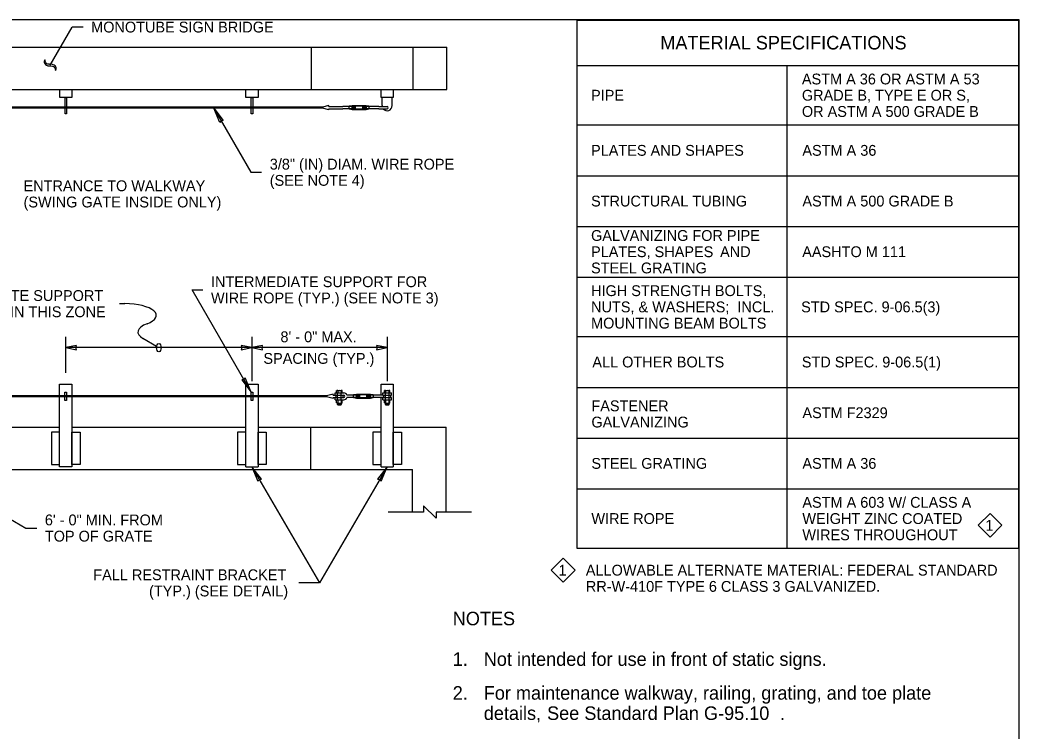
# Model space of a CAD drawing. Extents: x 99862 to 103151, y 100000 to 108076.
# Drawn here: x 101674 to 103151, y 101024 to 102076 of the extents above; entities that cross this region are included whole.
import ezdxf

# ---------------------------------------------------------------- set-up
doc = ezdxf.new("R2010")
doc.units = 0
for name, color, linetype in [('Level 1', 7, 'Continuous'), ('Level 11', 7, 'Continuous'), ('Level 14', 7, 'Continuous'), ('Level 15', 7, 'Continuous'), ('Level 18', 7, 'Continuous'), ('Level 2', 7, 'Continuous'), ('Level 20', 7, 'Continuous'), ('Level 23', 7, 'Continuous'), ('Level 3', 7, 'Continuous'), ('Level 4', 7, 'Continuous'), ('Level 60', 7, 'Continuous')]:
    doc.layers.add(name, color=color, linetype=linetype)

msp = doc.modelspace()

# ---------------------------------------------------------------- linework, layer by layer
at = {"layer": 'Level 1'}
msp.add_lwpolyline([(99862, 99999.5), (103151, 99999.5), (103151, 102075.5), (99862, 102075.5)], close=True, dxfattribs=at)
at = {"layer": 'Level 11'}
for p, q in [((102209.5, 101948.8), (102209.5, 101960.8)), ((102224.4, 101948.8), (102224.4, 101960.8)), ((102113.5, 101946.7), (101486.1, 101946.7)), ((102113.5, 101945), (101486.1, 101945)), ((102121.2, 101946.7), (102113.5, 101946.7)), ((102121.2, 101945), (102113.5, 101945)), ((102130.5, 101949.2), (102121.2, 101946.7)), ((102121.2, 101946.7), (102121.2, 101945)), ((102130.5, 101942.5), (102121.2, 101945)), ((102130.5, 101947.5), (102130.5, 101949.2)), ((102130.5, 101947.5), (102151.1, 101947.5)), ((102130.5, 101944.2), (102151.1, 101944.2)), ((102130.5, 101942.5), (102130.5, 101944.2)), ((102160.8, 101947.5), (102151.1, 101947.5)), ((102160.8, 101944.2), (102151.1, 101944.2)), ((102165.1, 101947.5), (102160.8, 101947.5)), ((102165.1, 101944.2), (102160.8, 101944.2)), ((102165.1, 101948.3), (102185.7, 101948.3)), ((102165.1, 101943.4), (102165.1, 101948.3)), ((102165.1, 101947.5), (102170, 101947.5)), ((102165.1, 101944.2), (102170, 101944.2)), ((102185.7, 101943.4), (102165.1, 101943.4)), ((102165.9, 101945), (102165.9, 101946.7)), ((102166.7, 101944.2), (102166.7, 101947.5)), ((102167.6, 101945), (102167.6, 101946.7)), ((102168.4, 101944.2), (102168.4, 101947.5)), ((102169.2, 101945), (102169.2, 101946.7)), ((102170, 101944.2), (102170, 101947.5)), ((102185.7, 101947.5), (102180.7, 101947.5)), ((102180.7, 101944.2), (102180.7, 101947.5)), ((102185.7, 101944.2), (102180.7, 101944.2)), ((102181.5, 101945), (102181.5, 101946.7)), ((102182.3, 101944.2), (102182.3, 101947.5)), ((102183.2, 101945), (102183.2, 101946.7)), ((102184, 101944.2), (102184, 101947.5)), ((102184.8, 101945), (102184.8, 101946.7)), ((102185.7, 101948.3), (102185.7, 101943.4)), ((102189.9, 101947.5), (102185.7, 101947.5)), ((102189.9, 101944.2), (102185.7, 101944.2)), ((102204.4, 101947.5), (102189.9, 101947.5)), ((102204.4, 101944.2), (102189.9, 101944.2)), ((102204.4, 101947.5), (102216.9, 101947.5)), ((102204.4, 101944.2), (102216.9, 101944.2))]:
    msp.add_line(p, q, dxfattribs=at)
for points in [[(101740.8, 101960.8), (101743, 101960.8), (101743, 101936.8), (101740.8, 101936.8)], [(102015.8, 101960.8), (102018.1, 101960.8), (102018.1, 101936.8), (102015.8, 101936.8)], [(102160.8, 101948.3), (102165, 101949.2), (102185.7, 101949.2), (102189.9, 101948.3), (102189.9, 101943.4), (102185.7, 101942.5), (102165, 101942.5), (102160.8, 101943.4)], [(101740.5, 101525), (101742.8, 101525), (101742.8, 101513), (101740.5, 101513)], [(102015.8, 101525), (102018.1, 101525), (102018.1, 101513), (102015.8, 101513)]]:
    msp.add_lwpolyline(points, close=True, dxfattribs=at)
for centre, radius, start, end in [((102216.9, 101948.8), 7.45, 180, 190.3619), ((102216.9, 101948.8), 7.45, 218.7191, 0), ((102216.9, 101945.8), 1.66, 270, 90)]:
    msp.add_arc(centre, radius, start, end, dxfattribs=at)
at = {"layer": 'Level 14'}
msp.add_line((101821.1, 101656), (101829.1, 101656), dxfattribs=at)
for centre, start_param, end_param in [((101829.1, 101638.6), 2.356226, 4.712389), ((101894.7, 101614), 5.497747, 6.859209)]:
    msp.add_ellipse(centre, major_axis=(-46.4, 0), ratio=0.375, start_param=start_param, end_param=end_param, dxfattribs=at)
at = {"layer": 'Level 15'}
for p, q in [((101718.7, 102008.7), (101751.2, 102065)), ((101767.2, 102065), (101751.2, 102065)), ((101960.6, 101945), (102015.3, 101850.3)), ((102015.3, 101850.3), (102031.3, 101850.3)), ((102015.8, 101525), (101928.4, 101676.4)), ((101928.4, 101676.4), (101944.4, 101676.4)), ((101741.6, 101553.5), (101741.6, 101607)), ((101876, 101592.9), (101855.8, 101604.5)), ((102017, 101607), (102017, 101541.5)), ((102216.9, 101607), (102216.9, 101541.5)), ((102017, 101591), (101741.6, 101591)), ((102216.9, 101591), (102017, 101591)), ((102017, 101414.8), (102116.9, 101243)), ((102216.9, 101414.8), (102116.9, 101243)), ((101605.6, 101368.7), (101682.8, 101324.2)), ((101682.8, 101324.2), (101698.8, 101324.2)), ((102116.9, 101243), (102086.3, 101243))]:
    msp.add_line(p, q, dxfattribs=at)
for points in [[(101960.6, 101945), (101974.6, 101926.7), (101971.5, 101926.2), (101969.4, 101923.7)], [(101741.6, 101591), (101757.4, 101587.9), (101756.6, 101591), (101757.4, 101594.1)], [(102017, 101591), (102001.2, 101594.1), (102002, 101591), (102001.2, 101587.9)], [(102017, 101591), (102032.7, 101587.9), (102032, 101591), (102032.7, 101594.1)], [(102017, 101591), (102032.7, 101587.9), (102032, 101591), (102032.7, 101594.1)], [(102216.9, 101591), (102201.2, 101594.1), (102201.9, 101591), (102201.2, 101587.9)], [(102015.8, 101525), (102007, 101546.3), (102005, 101543.8), (102001.8, 101543.3)], [(102017, 101414.8), (102025.9, 101393.5), (102027.9, 101395.9), (102031, 101396.5)], [(102216.9, 101414.8), (102202.8, 101396.5), (102205.9, 101395.9), (102208, 101393.5)]]:
    msp.add_lwpolyline(points, close=True, dxfattribs=at)
msp.add_lwpolyline([(102341.3, 101347.9), (102289.1, 101347.9), (102289.1, 101338.6), (102270.5, 101357.2), (102270.5, 101347.9), (102218.2, 101347.9)], dxfattribs=at)
msp.add_ellipse((101879.3, 101591), major_axis=(0, 6), ratio=0.57735, dxfattribs=at)
at = {"layer": 'Level 18'}
for p, q in [((102008, 101414.8), (102026, 101414.8)), ((102207.9, 101414.8), (102225.9, 101414.8))]:
    msp.add_line(p, q, dxfattribs=at)
for points in [[(101732.6, 101519.8), (101732.6, 101537), (101750.6, 101537), (101750.6, 101519.8)], [(102008, 101519.8), (102008, 101537), (102026, 101537), (102026, 101519.8)], [(102207.9, 101520.6), (102207.9, 101537), (102225.9, 101537), (102225.9, 101537)], [(102225.9, 101537), (102225.9, 101414.8)], [(101750.6, 101518.2), (101750.6, 101414.8), (101732.6, 101414.8), (101732.6, 101518.2)], [(102008, 101414.8), (102008, 101518.2)], [(102026, 101518.2), (102026, 101414.8)], [(102207.9, 101414.8), (102207.9, 101517.3)]]:
    msp.add_lwpolyline(points, dxfattribs=at)
for points in [[(101732.6, 101466.2), (101720.4, 101466.2), (101720.4, 101418.3), (101732.6, 101418.3)], [(101750.6, 101466.2), (101762.8, 101466.2), (101762.8, 101418.3), (101750.6, 101418.3)], [(102008, 101466.2), (101995.8, 101466.2), (101995.8, 101418.3), (102008, 101418.3)], [(102026, 101466.2), (102038.2, 101466.2), (102038.2, 101418.3), (102026, 101418.3)], [(102207.9, 101466.2), (102195.7, 101466.2), (102195.7, 101418.3), (102207.9, 101418.3)], [(102225.9, 101466.2), (102238.1, 101466.2), (102238.1, 101418.3), (102225.9, 101418.3)]]:
    msp.add_lwpolyline(points, close=True, dxfattribs=at)
at = {"layer": 'Level 2'}
for p, q in [((101510.2, 102035.3), (102305.1, 102035.3)), ((102105.1, 101972.8), (102105.1, 102035.3)), ((102255.1, 101972.8), (102255.1, 102035.3)), ((102305.1, 101972.8), (102305.1, 102035.3)), ((102305.1, 101972.8), (102305.1, 102035.3)), ((101510.2, 101972.8), (102305.1, 101972.8)), ((101509.1, 101473.5), (101732.6, 101473.5)), ((101750.6, 101473.5), (102008, 101473.5)), ((102026, 101473.5), (102207.9, 101473.5)), ((102104.1, 101411), (102104.1, 101473.5)), ((102225.9, 101473.5), (102304.1, 101473.5)), ((102304.1, 101347.9), (102304.1, 101473.5)), ((101509.1, 101411), (102254.1, 101411)), ((102254.1, 101347.9), (102254.1, 101411))]:
    msp.add_line(p, q, dxfattribs=at)
at = {"layer": 'Level 20'}
for p, q in [((101710.7, 102016.6), (101709.7, 102014.8)), ((101711.7, 102013.1), (101710.7, 102016.6)), ((101709.7, 102014.8), (101710, 102012.7)), ((101710, 102012.7), (101710.7, 102011)), ((101710.7, 102011), (101711.6, 102009.7)), ((101711.6, 102009.7), (101713, 102008.7)), ((101712.6, 102011.7), (101711.7, 102013.1)), ((101713.7, 102010.7), (101712.6, 102011.7)), ((101713, 102008.7), (101715.3, 102007.8)), ((101715.1, 102010.2), (101713.7, 102010.7)), ((101717.5, 102010), (101715.1, 102010.2)), ((101715.3, 102007.8), (101719.3, 102007.5)), ((101721.9, 102009.6), (101717.5, 102010)), ((101719.3, 102007.5), (101721.9, 102007.3)), ((101724.4, 102008.7), (101721.9, 102009.6)), ((101721.9, 102007.3), (101723.7, 102006.7)), ((101723.7, 102006.7), (101724.7, 102005.9)), ((101725.8, 102007.6), (101724.4, 102008.7)), ((101724.7, 102005.9), (101725.6, 102004.8)), ((101725.6, 102004.8), (101726.2, 102003.2)), ((101726.9, 102006.3), (101725.8, 102007.6)), ((101726.2, 102003.2), (101726.7, 102000.8)), ((101726.7, 102000.8), (101727.7, 102002.6)), ((101727.5, 102004.6), (101726.9, 102006.3)), ((101727.7, 102002.6), (101727.5, 102004.6))]:
    msp.add_line(p, q, dxfattribs=at)
for points in [[(103108.1, 101345.8), (103125.7, 101328.3), (103108.1, 101310.7), (103090.6, 101328.3)], [(102477, 101279.5), (102494.6, 101261.9), (102477, 101244.4), (102459.5, 101261.9)]]:
    msp.add_lwpolyline(points, close=True, dxfattribs=at)
at = {"layer": 'Level 23'}
for points in [[(101732.9, 101972.8), (101750.9, 101972.8), (101750.9, 101960.8), (101732.9, 101960.8)], [(102008, 101972.8), (102026, 101972.8), (102026, 101960.8), (102008, 101960.8)], [(102207.9, 101972.8), (102225.9, 101972.8), (102225.9, 101960.8), (102207.9, 101960.8)]]:
    msp.add_lwpolyline(points, close=True, dxfattribs=at)
at = {"layer": 'Level 3'}
for p, q in [((102497.7, 102008.3), (103150, 102008.3)), ((102807.8, 102008.3), (102807.8, 101294.1)), ((102497.7, 101920.2), (103150, 101920.2)), ((102497.7, 101845.2), (103150, 101845.2)), ((102497.7, 101770.3), (103150, 101770.3)), ((102497.7, 101695.3), (103150, 101695.3)), ((102497.7, 101607.2), (103150, 101607.2)), ((102497.7, 101532.2), (103150, 101532.2)), ((102497.7, 101457.3), (103150, 101457.3)), ((102497.7, 101382.3), (103150, 101382.3))]:
    msp.add_line(p, q, dxfattribs=at)
msp.add_lwpolyline([(102497.7, 102075), (103150, 102075), (103150, 101294.1), (102497.7, 101294.1)], close=True, dxfattribs=at)
at = {"layer": 'Level 4'}
for p, q in [((102119.8, 101519.8), (101480.4, 101519.8)), ((102119.8, 101518.2), (101480.4, 101518.2)), ((102127.4, 101519.8), (102119.8, 101519.8)), ((102127.4, 101518.2), (102119.8, 101518.2)), ((102136.8, 101522.3), (102127.4, 101519.8)), ((102127.4, 101519.8), (102127.4, 101518.2)), ((102136.8, 101515.7), (102127.4, 101518.2)), ((102136.8, 101520.6), (102136.8, 101522.3)), ((102136.8, 101520.6), (102152.6, 101520.6)), ((102136.8, 101517.3), (102152.6, 101517.3)), ((102136.8, 101515.7), (102136.8, 101517.3)), ((102140.1, 101524), (102152.6, 101524)), ((102140.1, 101520.6), (102140.1, 101524)), ((102140.1, 101514), (102140.1, 101517.3)), ((102140.1, 101514), (102152.6, 101514)), ((102142.2, 101524), (102142.2, 101527.4)), ((102142.2, 101514), (102150.5, 101514)), ((102142.2, 101509.2), (102142.2, 101514)), ((102143.1, 101527.7), (102149.6, 101527.7)), ((102143.6, 101514), (102143.6, 101524)), ((102144, 101527.4), (102144, 101524)), ((102144, 101514), (102144, 101509.2)), ((102148.7, 101527.4), (102148.7, 101524)), ((102148.7, 101514), (102148.7, 101509.2)), ((102149.1, 101514), (102149.1, 101524)), ((102150.5, 101524), (102150.5, 101527.4)), ((102150.5, 101509.2), (102150.5, 101514)), ((102167.1, 101520.6), (102157.4, 101520.6)), ((102167.1, 101517.3), (102157.4, 101517.3)), ((102171.3, 101520.6), (102167.1, 101520.6)), ((102171.3, 101517.3), (102167.1, 101517.3)), ((102171.3, 101521.5), (102191.9, 101521.5)), ((102171.3, 101516.5), (102171.3, 101521.5)), ((102171.3, 101520.6), (102176.3, 101520.6)), ((102171.3, 101517.3), (102176.3, 101517.3)), ((102191.9, 101516.5), (102171.3, 101516.5)), ((102172.2, 101518.2), (102172.2, 101519.8)), ((102173, 101517.3), (102173, 101520.6)), ((102173.8, 101518.2), (102173.8, 101519.8)), ((102174.7, 101517.3), (102174.7, 101520.6)), ((102175.5, 101518.2), (102175.5, 101519.8)), ((102176.3, 101517.3), (102176.3, 101520.6)), ((102191.9, 101520.6), (102186.9, 101520.6)), ((102186.9, 101517.3), (102186.9, 101520.6)), ((102191.9, 101517.3), (102186.9, 101517.3)), ((102187.8, 101518.2), (102187.8, 101519.8)), ((102188.6, 101517.3), (102188.6, 101520.6)), ((102189.4, 101518.2), (102189.4, 101519.8)), ((102190.3, 101517.3), (102190.3, 101520.6)), ((102191.1, 101518.2), (102191.1, 101519.8)), ((102191.9, 101521.5), (102191.9, 101516.5)), ((102196.2, 101520.6), (102191.9, 101520.6)), ((102196.2, 101517.3), (102191.9, 101517.3)), ((102210.6, 101520.6), (102196.2, 101520.6)), ((102210.6, 101517.3), (102196.2, 101517.3)), ((102210.6, 101524), (102223.2, 101524)), ((102210.6, 101520.6), (102210.6, 101524)), ((102210.6, 101520.6), (102223.2, 101520.6)), ((102210.6, 101517.3), (102223.2, 101517.3)), ((102210.6, 101514), (102210.6, 101517.3)), ((102210.6, 101514), (102223.2, 101514)), ((102212.8, 101524), (102212.8, 101527.4)), ((102212.8, 101514), (102221, 101514)), ((102212.8, 101509.2), (102212.8, 101514)), ((102213.6, 101527.7), (102220.1, 101527.7)), ((102214.2, 101514), (102214.2, 101524)), ((102214.5, 101527.4), (102214.5, 101524)), ((102214.5, 101514), (102214.5, 101509.2)), ((102219.3, 101527.4), (102219.3, 101524)), ((102219.3, 101514), (102219.3, 101509.2)), ((102219.6, 101514), (102219.6, 101524)), ((102221, 101524), (102221, 101527.4)), ((102221, 101509.2), (102221, 101514)), ((102223.2, 101520.6), (102223.2, 101524)), ((102223.2, 101514), (102223.2, 101517.3)), ((102143.1, 101508.9), (102149.6, 101508.9)), ((102143.6, 101506.9), (102143.6, 101508.9)), ((102143.6, 101507.9), (102149.1, 101507.9)), ((102143.6, 101506.9), (102149.1, 101506.9)), ((102143.6, 101506.9), (102143.9, 101506.4)), ((102143.9, 101506.4), (102148.8, 101506.4)), ((102144.4, 101508.4), (102148.3, 101508.4)), ((102144.4, 101507.4), (102148.3, 101507.4)), ((102149.1, 101506.9), (102148.8, 101506.4)), ((102149.1, 101506.9), (102149.1, 101508.9)), ((102213.6, 101508.9), (102220.1, 101508.9)), ((102214.2, 101506.9), (102214.2, 101508.9)), ((102214.2, 101507.9), (102219.6, 101507.9)), ((102214.2, 101506.9), (102219.6, 101506.9)), ((102214.2, 101506.9), (102214.5, 101506.4)), ((102214.5, 101506.4), (102219.4, 101506.4)), ((102215, 101508.4), (102218.8, 101508.4)), ((102215, 101507.4), (102218.8, 101507.4)), ((102219.6, 101506.9), (102219.4, 101506.4)), ((102219.6, 101506.9), (102219.6, 101508.9))]:
    msp.add_line(p, q, dxfattribs=at)
msp.add_lwpolyline([(102167.1, 101521.5), (102171.3, 101522.3), (102192, 101522.3), (102196.2, 101521.5), (102196.2, 101516.5), (102192, 101515.7), (102171.3, 101515.7), (102167.1, 101516.5)], close=True, dxfattribs=at)
for centre, radius, start, end in [((102142.9, 101519), 2.22, 131.7358, 228.2642), ((102143.1, 101526.2), 1.5, 54.7199, 125.2801), ((102146.4, 101517.3), 10.3, 76.7504, 103.2496), ((102149.6, 101526.2), 1.5, 54.7199, 125.2801), ((102149.8, 101519), 2.22, 311.7358, 47.4328), ((102152.6, 101519), 5.03, 19.2502, 90), ((102152.6, 101519), 1.66, 270, 90), ((102152.6, 101519), 5.03, 270, 340.7483), ((102213.5, 101519), 2.22, 131.7358, 228.2642), ((102213.7, 101526.2), 1.5, 54.7199, 125.2801), ((102216.9, 101517.3), 10.3, 76.7504, 103.2496), ((102220.1, 101526.2), 1.5, 54.7199, 125.2801), ((102220.3, 101519), 2.22, 311.7358, 48.2642), ((102143.1, 101510.4), 1.5, 234.7199, 305.2801), ((102146.4, 101519.2), 10.3, 256.7504, 283.2496), ((102149.6, 101510.4), 1.5, 234.7199, 305.2801), ((102213.7, 101510.4), 1.5, 234.7199, 305.2801), ((102216.9, 101519.2), 10.3, 256.7504, 283.2496), ((102220.1, 101510.4), 1.5, 234.7199, 305.2801)]:
    msp.add_arc(centre, radius, start, end, dxfattribs=at)
at = {"layer": 'Level 60'}
msp.add_line((103151, 102075.5), (103151, 102075.5), dxfattribs=at)

# ---------------------------------------------------------------- texts
at = {"layer": 'Level 20'}
for s, height, p in [('MONOTUBE SIGN BRIDGE', 16, (101779.2, 102057)), ('MATERIAL SPECIFICATIONS', 20, (102620.7, 102031.9)), ('ASTM A 36 OR ASTM A 53', 16, (102830, 101980.2)), ('PIPE', 16, (102518.3, 101956.2)), ('GRADE B, TYPE E OR S,', 16, (102830, 101956.2)), ('OR ASTM A 500 GRADE B', 16, (102830, 101932.2)), ('PLATES AND SHAPES', 16, (102518.3, 101874.7)), ('ASTM A 36', 16, (102830.7, 101874.7)), ('3/8" (IN) DIAM. WIRE ROPE', 16, (102043.3, 101854.3)), ('ENTRANCE TO WALKWAY', 16, (101679.3, 101822.3)), ('(SEE NOTE 4)', 16, (102043.3, 101830.3)), ('(SWING GATE INSIDE ONLY)', 16, (101679.3, 101798.3)), ('STRUCTURAL TUBING', 16, (102518.3, 101799.7)), ('ASTM A 500 GRADE B', 16, (102830.7, 101799.7)), ('GALVANIZING FOR PIPE', 16, (102518.3, 101748.8)), ('PLATES, SHAPES', 16, (102518.3, 101724.8)), (' AND', 16, (102703.1, 101724.8)), ('AASHTO M 111', 16, (102830.5, 101724.8)), ('STEEL GRATING', 16, (102518.3, 101700.8)), ('INTERMEDIATE SUPPORT FOR', 16, (101956.4, 101680.4)), ('SAFETY CABLE AND INTERMEDIATE SUPPORT', 16, (101312, 101660)), ('HIGH STRENGTH BOLTS,', 16, (102518.3, 101667.2)), ('WIRE ROPE (TYP.) (SEE NOTE 3)', 16, (101956.4, 101656.4)), ('ARE OPTIONAL IN THIS ZONE', 16, (101495.2, 101636)), ('NUTS, & WASHERS;  INCL.', 16, (102518.3, 101643.2)), ('STD SPEC. 9-06.5(3)', 16, (102828.9, 101643.2)), ('MOUNTING BEAM BOLTS', 16, (102518.3, 101619.2)), ('8\' - 0" MAX.', 16, (102059.1, 101599)), ('SPACING (TYP.)', 16, (102033.9, 101567)), ('ALL OTHER BOLTS', 16, (102520.2, 101561.7)), ('STD SPEC. 9-06.5(1)', 16, (102829.9, 101561.7)), ('FASTENER', 16, (102518.8, 101496.9)), ('ASTM F2329', 16, (102830.8, 101486.7)), ('GALVANIZING', 16, (102518.8, 101472.9)), ('STEEL GRATING', 16, (102518.8, 101411.8)), ('ASTM A 36', 16, (102830.7, 101411.8)), ('ASTM A 603 W/ CLASS A', 16, (102830.7, 101354.2)), ('6\' - 0" MIN. FROM', 16, (101710.8, 101328.2)), ('WIRE ROPE', 16, (102518.8, 101330.2)), ('WEIGHT ZINC COATED', 16, (102830.7, 101330.2)), ('1', 16, (103101.3, 101320.3)), ('WIRES THROUGHOUT', 16, (102830.7, 101306.2)), ('TOP OF GRATE', 16, (101710.8, 101304.2)), ('FALL RESTRAINT BRACKET', 16, (101782.4, 101247.1)), ('1', 16, (102470.2, 101253.9)), ('ALLOWABLE ALTERNATE MATERIAL: FEDERAL STANDARD', 16, (102510.6, 101253.9)), ('(TYP.) (SEE DETAIL)', 16, (101864.8, 101223.1)), ('RR-W-410F TYPE 6 CLASS 3 GALVANIZED.', 16, (102510.6, 101229.9)), ('NOTES', 20, (102313.8, 101180.4)), ('1.', 20, (102313.8, 101120.4)), ('Not intended for use in front of static signs.', 20, (102359.7, 101120.4)), ('2.', 20, (102313.8, 101070.4)), ('For maintenance walkway, railing, grating, and toe plate', 20, (102359.7, 101070.4)), ('details, ', 20, (102359.7, 101040.4)), ('See Standard Plan G-95.10', 20, (102453.3, 101040.4)), ('.', 20, (102797.5, 101040.4))]:
    msp.add_text(s, height=height, dxfattribs=at).set_placement(p)

doc.saveas('drawing.dxf')
